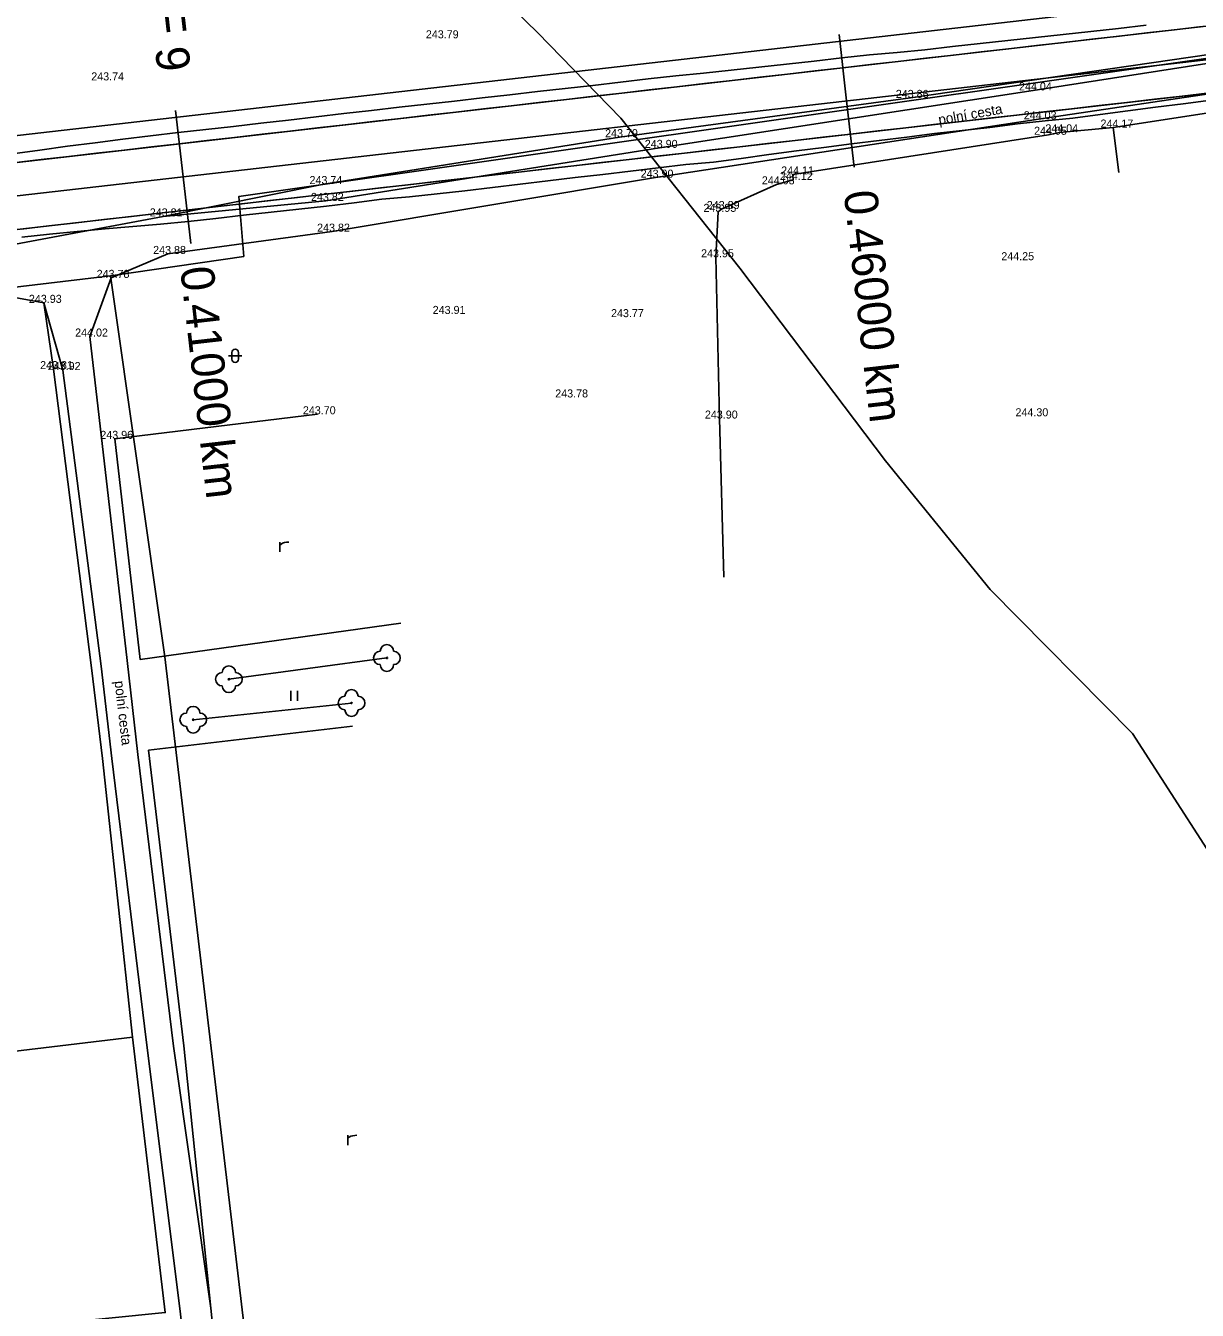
# Model space of a CAD drawing. Extents: x -555887 to -552101, y -1100251 to -1096546.
# Drawn here: x -554377.8 to -554290.1, y -1097745.7 to -1097649.6 of the extents above; entities that cross this region are included whole.
import ezdxf

# ---------------------------------------------------------------- set-up
doc = ezdxf.new("R2010")
doc.units = 0
for name, color, linetype in [('PARCELY_cesty', 7, 'Continuous'), ('POLYGONY_SITUACE_PF', 7, 'Continuous'), ('POLYGONY_SITUACE_PF_POPISY', 7, 'Continuous'), ('POLYGONY_SITUACE_PO', 7, 'Continuous'), ('vrstevnice', 7, 'Continuous'), ('Výškopis', 7, 'Continuous'), ('ZSST', 7, 'Continuous'), ('zájem', 7, 'Continuous')]:
    doc.layers.add(name, color=color, linetype=linetype)

msp = doc.modelspace()

# ---------------------------------------------------------------- linework, layer by layer
at = {"layer": 'PARCELY_cesty'}
msp.add_lwpolyline([(-554491.8, -1097670.76), (-554258.37, -1097644.02)], dxfattribs=at)
at = {"layer": 'POLYGONY_SITUACE_PF'}
for p, q in [((-554316.95, -1097650.231), (-554316.381, -1097655.199)), ((-554316.381, -1097655.199), (-554315.812, -1097660.166)), ((-554366.625, -1097655.921), (-554366.056, -1097660.888)), ((-554366.056, -1097660.888), (-554365.487, -1097665.856))]:
    msp.add_line(p, q, dxfattribs=at)
at = {"layer": 'POLYGONY_SITUACE_PO'}
for p, q in [((-554247.533, -1097644.797), (-554424.295, -1097665.042)), ((-554490.653, -1097675.159), (-554241.626, -1097646.637)), ((-554298.103, -1097650.012), (-554300.174, -1097650.233)), ((-554296.032, -1097649.785), (-554298.103, -1097650.012)), ((-554293.963, -1097649.536), (-554296.032, -1097649.785)), ((-554293.898, -1097650.108), (-554291.828, -1097649.87)), ((-554291.828, -1097649.87), (-554289.758, -1097649.633)), ((-554444.424, -1097672.38), (-554255.551, -1097650.748)), ((-554306.388, -1097650.905), (-554308.459, -1097651.133)), ((-554304.317, -1097650.68), (-554306.388, -1097650.905)), ((-554302.246, -1097650.455), (-554304.317, -1097650.68)), ((-554300.174, -1097650.233), (-554302.246, -1097650.455)), ((-554302.177, -1097651.056), (-554300.107, -1097650.819)), ((-554300.107, -1097650.819), (-554298.037, -1097650.582)), ((-554298.037, -1097650.582), (-554295.968, -1097650.345)), ((-554295.968, -1097650.345), (-554293.898, -1097650.108)), ((-554314.679, -1097651.755), (-554316.75, -1097651.981)), ((-554312.604, -1097651.561), (-554314.679, -1097651.755)), ((-554310.53, -1097651.361), (-554312.604, -1097651.561)), ((-554308.459, -1097651.133), (-554310.53, -1097651.361)), ((-554310.456, -1097652.004), (-554308.386, -1097651.767)), ((-554308.386, -1097651.767), (-554306.317, -1097651.53)), ((-554306.317, -1097651.53), (-554304.247, -1097651.293)), ((-554304.247, -1097651.293), (-554302.177, -1097651.056)), ((-554325.032, -1097652.904), (-554327.104, -1097653.115)), ((-554322.961, -1097652.674), (-554325.032, -1097652.904)), ((-554320.891, -1097652.443), (-554322.961, -1097652.674)), ((-554318.82, -1097652.212), (-554320.891, -1097652.443)), ((-554316.75, -1097651.981), (-554318.82, -1097652.212)), ((-554318.735, -1097652.952), (-554316.666, -1097652.715)), ((-554316.666, -1097652.715), (-554314.596, -1097652.478)), ((-554314.596, -1097652.478), (-554312.526, -1097652.241)), ((-554312.526, -1097652.241), (-554310.456, -1097652.004)), ((-554333.317, -1097653.803), (-554335.385, -1097654.049)), ((-554331.25, -1097653.535), (-554333.317, -1097653.803)), ((-554329.179, -1097653.313), (-554331.25, -1097653.535)), ((-554327.104, -1097653.115), (-554329.179, -1097653.313)), ((-554329.084, -1097654.138), (-554327.015, -1097653.9)), ((-554327.015, -1097653.9), (-554324.945, -1097653.663)), ((-554324.945, -1097653.663), (-554322.875, -1097653.426)), ((-554322.875, -1097653.426), (-554320.805, -1097653.189)), ((-554320.805, -1097653.189), (-554318.735, -1097652.952)), ((-554341.598, -1097654.733), (-554343.667, -1097654.974)), ((-554339.528, -1097654.495), (-554341.598, -1097654.733)), ((-554337.457, -1097654.273), (-554339.528, -1097654.495)), ((-554335.385, -1097654.049), (-554337.457, -1097654.273)), ((-554337.364, -1097655.086), (-554335.294, -1097654.849)), ((-554335.294, -1097654.849), (-554333.224, -1097654.612)), ((-554333.224, -1097654.612), (-554331.154, -1097654.375)), ((-554331.154, -1097654.375), (-554329.084, -1097654.138)), ((-554293.329, -1097655.075), (-554291.259, -1097654.838)), ((-554291.259, -1097654.838), (-554289.189, -1097654.601)), ((-554349.879, -1097655.669), (-554351.948, -1097655.906)), ((-554347.807, -1097655.451), (-554349.879, -1097655.669)), ((-554345.736, -1097655.217), (-554347.807, -1097655.451)), ((-554343.667, -1097654.974), (-554345.736, -1097655.217)), ((-554345.643, -1097656.034), (-554343.573, -1097655.797)), ((-554343.573, -1097655.797), (-554341.503, -1097655.56)), ((-554341.503, -1097655.56), (-554339.433, -1097655.323)), ((-554339.433, -1097655.323), (-554337.364, -1097655.086)), ((-554301.608, -1097656.023), (-554299.538, -1097655.786)), ((-554299.538, -1097655.786), (-554297.468, -1097655.549)), ((-554297.468, -1097655.549), (-554295.399, -1097655.312)), ((-554295.399, -1097655.312), (-554293.329, -1097655.075)), ((-554295.327, -1097655.935), (-554293.261, -1097655.67)), ((-554293.261, -1097655.67), (-554291.194, -1097655.402)), ((-554291.194, -1097655.402), (-554289.128, -1097655.135)), ((-554358.157, -1097656.627), (-554360.226, -1097656.869)), ((-554356.087, -1097656.384), (-554358.157, -1097656.627)), ((-554354.018, -1097656.143), (-554356.087, -1097656.384)), ((-554351.948, -1097655.906), (-554354.018, -1097656.143)), ((-554353.922, -1097656.982), (-554351.852, -1097656.745)), ((-554351.852, -1097656.745), (-554349.782, -1097656.508)), ((-554349.782, -1097656.508), (-554347.713, -1097656.271)), ((-554347.713, -1097656.271), (-554345.643, -1097656.034)), ((-554309.887, -1097656.972), (-554307.817, -1097656.734)), ((-554307.817, -1097656.734), (-554305.748, -1097656.497)), ((-554305.748, -1097656.497), (-554303.678, -1097656.26)), ((-554303.678, -1097656.26), (-554301.608, -1097656.023)), ((-554303.604, -1097656.908), (-554301.531, -1097656.697)), ((-554301.531, -1097656.697), (-554299.458, -1097656.485)), ((-554299.458, -1097656.485), (-554297.392, -1097656.212)), ((-554297.392, -1097656.212), (-554295.327, -1097655.935)), ((-554366.437, -1097657.563), (-554368.507, -1097657.804)), ((-554364.367, -1097657.334), (-554366.437, -1097657.563)), ((-554362.296, -1097657.104), (-554364.367, -1097657.334)), ((-554360.226, -1097656.869), (-554362.296, -1097657.104)), ((-554362.201, -1097657.93), (-554360.131, -1097657.693)), ((-554360.131, -1097657.693), (-554358.062, -1097657.456)), ((-554358.062, -1097657.456), (-554355.992, -1097657.219)), ((-554355.992, -1097657.219), (-554353.922, -1097656.982)), ((-554318.166, -1097657.92), (-554316.097, -1097657.683)), ((-554316.097, -1097657.683), (-554314.027, -1097657.446)), ((-554314.027, -1097657.446), (-554311.957, -1097657.209)), ((-554311.957, -1097657.209), (-554309.887, -1097656.972)), ((-554311.877, -1097657.905), (-554309.81, -1097657.643)), ((-554309.81, -1097657.643), (-554307.739, -1097657.419)), ((-554307.739, -1097657.419), (-554305.669, -1097657.185)), ((-554305.669, -1097657.185), (-554303.604, -1097656.908)), ((-554374.707, -1097658.591), (-554376.772, -1097658.87)), ((-554372.641, -1097658.324), (-554374.707, -1097658.591)), ((-554370.574, -1097658.062), (-554372.641, -1097658.324)), ((-554368.507, -1097657.804), (-554370.574, -1097658.062)), ((-554370.48, -1097658.879), (-554368.411, -1097658.642)), ((-554368.411, -1097658.642), (-554366.341, -1097658.405)), ((-554366.341, -1097658.405), (-554364.271, -1097658.167)), ((-554364.271, -1097658.167), (-554362.201, -1097657.93)), ((-554326.446, -1097658.868), (-554324.376, -1097658.631)), ((-554324.376, -1097658.631), (-554322.306, -1097658.394)), ((-554322.306, -1097658.394), (-554320.236, -1097658.157)), ((-554320.236, -1097658.157), (-554318.166, -1097657.92)), ((-554320.147, -1097658.936), (-554318.08, -1097658.674)), ((-554318.08, -1097658.674), (-554316.013, -1097658.413)), ((-554316.013, -1097658.413), (-554313.946, -1097658.151)), ((-554313.946, -1097658.151), (-554311.877, -1097657.905)), ((-554376.772, -1097658.87), (-554378.837, -1097659.153)), ((-554378.76, -1097659.827), (-554376.69, -1097659.59)), ((-554376.69, -1097659.59), (-554374.62, -1097659.353)), ((-554374.62, -1097659.353), (-554372.55, -1097659.116)), ((-554372.55, -1097659.116), (-554370.48, -1097658.879)), ((-554334.725, -1097659.816), (-554332.655, -1097659.579)), ((-554332.655, -1097659.579), (-554330.585, -1097659.342)), ((-554330.585, -1097659.342), (-554328.515, -1097659.105)), ((-554328.515, -1097659.105), (-554326.446, -1097658.868)), ((-554326.342, -1097659.771), (-554324.277, -1097659.495)), ((-554324.277, -1097659.495), (-554322.213, -1097659.209)), ((-554322.213, -1097659.209), (-554320.147, -1097658.936)), ((-554343.004, -1097660.764), (-554340.934, -1097660.527)), ((-554340.934, -1097660.527), (-554338.864, -1097660.29)), ((-554338.864, -1097660.29), (-554336.795, -1097660.053)), ((-554336.795, -1097660.053), (-554334.725, -1097659.816)), ((-554334.624, -1097660.699), (-554332.553, -1097660.466)), ((-554332.553, -1097660.466), (-554330.485, -1097660.216)), ((-554330.485, -1097660.216), (-554328.418, -1097659.953)), ((-554328.418, -1097659.953), (-554326.342, -1097659.771)), ((-554351.283, -1097661.713), (-554349.213, -1097661.476)), ((-554349.213, -1097661.476), (-554347.144, -1097661.239)), ((-554347.144, -1097661.239), (-554345.074, -1097661.001)), ((-554345.074, -1097661.001), (-554343.004, -1097660.764)), ((-554342.9, -1097661.677), (-554340.831, -1097661.431)), ((-554340.831, -1097661.431), (-554338.764, -1097661.168)), ((-554338.764, -1097661.168), (-554336.694, -1097660.932)), ((-554336.694, -1097660.932), (-554334.624, -1097660.699)), ((-554359.562, -1097662.661), (-554357.493, -1097662.424)), ((-554357.493, -1097662.424), (-554355.423, -1097662.187)), ((-554355.423, -1097662.187), (-554353.353, -1097661.95)), ((-554353.353, -1097661.95), (-554351.283, -1097661.713)), ((-554353.253, -1097662.82), (-554351.187, -1097662.549)), ((-554351.187, -1097662.549), (-554349.11, -1097662.377)), ((-554349.11, -1097662.377), (-554347.04, -1097662.146)), ((-554347.04, -1097662.146), (-554344.969, -1097661.915)), ((-554344.969, -1097661.915), (-554342.9, -1097661.677)), ((-554367.842, -1097663.609), (-554365.772, -1097663.372)), ((-554365.772, -1097663.372), (-554363.702, -1097663.135)), ((-554363.702, -1097663.135), (-554361.632, -1097662.898)), ((-554361.632, -1097662.898), (-554359.562, -1097662.661)), ((-554359.463, -1097663.528), (-554357.392, -1097663.303)), ((-554357.392, -1097663.303), (-554355.321, -1097663.079)), ((-554355.321, -1097663.079), (-554353.253, -1097662.82)), ((-554376.121, -1097664.557), (-554374.051, -1097664.32)), ((-554374.051, -1097664.32), (-554371.981, -1097664.083)), ((-554371.981, -1097664.083), (-554369.911, -1097663.846)), ((-554369.911, -1097663.846), (-554367.842, -1097663.609)), ((-554369.824, -1097664.606), (-554367.749, -1097664.417)), ((-554367.749, -1097664.417), (-554365.675, -1097664.22)), ((-554365.675, -1097664.22), (-554363.603, -1097664.003)), ((-554363.603, -1097664.003), (-554361.534, -1097663.755)), ((-554361.534, -1097663.755), (-554359.463, -1097663.528)), ((-554378.191, -1097664.794), (-554376.121, -1097664.557)), ((-554378.123, -1097665.382), (-554376.05, -1097665.174)), ((-554376.05, -1097665.174), (-554373.977, -1097664.971)), ((-554373.977, -1097664.971), (-554371.903, -1097664.766)), ((-554371.903, -1097664.766), (-554369.824, -1097664.606))]:
    msp.add_line(p, q, dxfattribs=at)
at = {"layer": 'vrstevnice'}
msp.add_lwpolyline([(-554347.025, -1097642.766), (-554339.532, -1097650.07), (-554333.287, -1097656.484), (-554324.367, -1097667.707), (-554313.484, -1097682.137), (-554305.633, -1097691.757), (-554294.981, -1097702.544), (-554286.519, -1097715.669), (-554277.696, -1097733.469), (-554269.053, -1097748.571), (-554262.931, -1097761.696), (-554258.429, -1097773.562), (-554253.928, -1097784.53), (-554249.066, -1097795.138), (-554243.124, -1097805.925), (-554239.79, -1097811.633), (-554234.452, -1097818.091), (-554228.293, -1097825.881), (-554221.415, -1097824.856), (-554212.484, -1097831.621)], dxfattribs=at)
at = {"layer": 'ZSST'}
for p, q in [((-554296.42, -1097657.19), (-554296.016, -1097660.556)), ((-554325.75, -1097663.29), (-554321.63, -1097661.44)), ((-554362.406, -1097674.523), (-554362.406, -1097674.023)), ((-554361.906, -1097674.523), (-554361.906, -1097674.023)), ((-554361.656, -1097674.273), (-554362.656, -1097674.273)), ((-554362.63, -1097698.48), (-554350.8, -1097696.89)), ((-554357.982, -1097700.105), (-554357.982, -1097699.355)), ((-554357.482, -1097700.105), (-554357.482, -1097699.355)), ((-554365.3, -1097701.51), (-554353.45, -1097700.26))]:
    msp.add_line(p, q, dxfattribs=at)
for points in [[(-554367.55, -1097663.84), (-554355.51, -1097661.42), (-554333.39, -1097657.91), (-554311.6, -1097654.97), (-554277.06, -1097649.95), (-554267.08, -1097648.22), (-554259.77, -1097645.47), (-554254.71, -1097640.31), (-554251.15, -1097635.05)], [(-554256.64, -1097648.34), (-554263.67, -1097648.69), (-554270.36, -1097649.56), (-554286.06, -1097651.86), (-554302.41, -1097654.41), (-554330.39, -1097658.71), (-554355.36, -1097662.68), (-554367.55, -1097663.84)], [(-554367.19, -1097666.65), (-554354.9, -1097664.98), (-554330.7, -1097660.94), (-554302.03, -1097656.57), (-554286.07, -1097654.18), (-554270.52, -1097651.57), (-554263.57, -1097650.92), (-554256.9, -1097650.3)], [(-554300.44, -1097657.55), (-554296.42, -1097657.19), (-554286.21, -1097655.61), (-554270.39, -1097653.56), (-554254.78, -1097651.65)], [(-554321.63, -1097661.44), (-554320.39, -1097661.11), (-554320.42, -1097660.7), (-554301.26, -1097657.73), (-554300.44, -1097657.55)], [(-554326.17, -1097666.9), (-554325.99, -1097663.5), (-554325.75, -1097663.29)], [(-554454.89, -1097678.09), (-554427.97, -1097673.93), (-554391.64, -1097668.01), (-554379.83, -1097666.15), (-554367.55, -1097663.84)], [(-554367.19, -1097666.65), (-554371.44, -1097668.44), (-554373.04, -1097672.83), (-554370.25, -1097697.08), (-554369.44, -1097704.12), (-554366.77, -1097725.95), (-554363.98, -1097745.55), (-554362.21, -1097763.14), (-554359.85, -1097780.61), (-554353.51, -1097814.44), (-554351.69, -1097818.85), (-554348.87, -1097819.47), (-554340.38, -1097818.88)], [(-554325.57, -1097690.83), (-554325.89, -1097678.97), (-554326.17, -1097666.9)], [(-554375.07, -1097675.34), (-554376.48, -1097670.31), (-554380.31, -1097669.62), (-554391.09, -1097670.89), (-554427.26, -1097676.93), (-554454.67, -1097680.77), (-554487.61, -1097685.6), (-554502.67, -1097687.9), (-554507.97, -1097691.12), (-554509.75, -1097693.98), (-554508.52, -1097711.87), (-554506.18, -1097742.54), (-554505.38, -1097760.57), (-554505.26, -1097765.99), (-554503.94, -1097783.38), (-554503.38, -1097798.36), (-554502.89, -1097806.7), (-554501.1, -1097825.65), (-554499.52, -1097860.36), (-554498.38, -1097882.55), (-554497.18, -1097896.97), (-554493.27, -1097934.67), (-554492.2, -1097940.22), (-554491.25, -1097941.81)], [(-554376.48, -1097670.31), (-554375.76, -1097675.27), (-554372.91, -1097697.64), (-554372.08, -1097704.42), (-554369.85, -1097725.28), (-554422.57, -1097731.58), (-554455.2, -1097735.79), (-554506.18, -1097742.54)], [(-554340.06, -1097820.97), (-554346.72, -1097821.89), (-554350.25, -1097823.77), (-554351.16, -1097827.36), (-554349.96, -1097836.43), (-554351.78, -1097836.52), (-554353.39, -1097827.68), (-554355.71, -1097814.51), (-554362.18, -1097781.05), (-554364.28, -1097763.5), (-554366.28, -1097745.77), (-554368.82, -1097725.46), (-554371.39, -1097704.41), (-554372.2, -1097697.51), (-554375.07, -1097675.34)], [(-554356, -1097678.65), (-554371.16, -1097680.49), (-554369.28, -1097697), (-554349.76, -1097694.29)], [(-554358.823, -1097688.955), (-554358.823, -1097688.223)], [(-554358.823, -1097688.459), (-554358.721, -1097688.364), (-554358.618, -1097688.301), (-554358.461, -1097688.254), (-554358.311, -1097688.231), (-554358.154, -1097688.223)], [(-554353.38, -1097701.99), (-554368.64, -1097703.8), (-554366, -1097725.91), (-554363.98, -1097745.55)], [(-554505.38, -1097760.57), (-554420.27, -1097751.2), (-554367.39, -1097745.88), (-554369.85, -1097725.28)], [(-554353.717, -1097733.347), (-554353.717, -1097732.615)], [(-554353.717, -1097732.851), (-554353.615, -1097732.756), (-554353.512, -1097732.693), (-554353.355, -1097732.646), (-554353.205, -1097732.623), (-554353.048, -1097732.615)]]:
    msp.add_lwpolyline(points, dxfattribs=at)
for centre in [(-554350.8, -1097696.89), (-554362.63, -1097698.48), (-554353.45, -1097700.26), (-554365.3, -1097701.51)]:
    msp.add_circle(centre, 0.05, dxfattribs=at)
for centre, radius, start, end in [((-554362.156, -1097674.023), 0.25, 0, 180), ((-554362.156, -1097674.523), 0.25, 180, 0), ((-554350.8, -1097696.39), 0.5, 0, 180), ((-554351.3, -1097696.89), 0.5, 90, 270), ((-554350.3, -1097696.89), 0.5, 270, 90), ((-554363.13, -1097698.48), 0.5, 90, 270), ((-554362.63, -1097697.98), 0.5, 0, 180), ((-554362.13, -1097698.48), 0.5, 270, 90), ((-554350.8, -1097697.39), 0.5, 180, 0), ((-554362.63, -1097698.98), 0.5, 180, 0), ((-554353.95, -1097700.26), 0.5, 90, 270), ((-554353.45, -1097699.76), 0.5, 0, 180), ((-554352.95, -1097700.26), 0.5, 270, 90), ((-554365.8, -1097701.51), 0.5, 90, 270), ((-554365.3, -1097701.01), 0.5, 0, 180), ((-554364.8, -1097701.51), 0.5, 270, 90), ((-554353.45, -1097700.76), 0.5, 180, 0), ((-554365.3, -1097702.01), 0.5, 180, 0)]:
    msp.add_arc(centre, radius, start, end, dxfattribs=at)
at = {"layer": 'zájem'}
for points in [[(-554254.33, -1097646.97), (-554361.88, -1097662.34), (-554361.52, -1097666.83), (-554371.48, -1097668.3), (-554500.56, -1097683.64)], [(-554187.71, -1098013.33), (-554235.08, -1098020.43), (-554238.75, -1098020.74), (-554242.36, -1098021.18), (-554261.03, -1098023.47), (-554275.16, -1097920.72), (-554275.98, -1097914.73), (-554338.17, -1097921.77), (-554343.92, -1097894.3), (-554344.86, -1097865.76), (-554349.69, -1097836.21), (-554354.15, -1097808.8), (-554357.5, -1097780.42), (-554360.83, -1097752.42), (-554364.23, -1097723.78), (-554367.43, -1097696.8), (-554371.48, -1097668.3), (-554361.52, -1097666.83), (-554361.88, -1097662.34), (-554254.33, -1097646.97)]]:
    msp.add_lwpolyline(points, dxfattribs=at)

# ---------------------------------------------------------------- texts
at = {"layer": 'POLYGONY_SITUACE_PF_POPISY'}
for s, p in [('PF 9', (-554368.757, -1097646.1)), ('0.46000 km', (-554316.606, -1097662.022)), ('0.41000 km', (-554366.281, -1097667.711))]:
    msp.add_text(s, height=2.5, rotation=276.5337, dxfattribs=at).set_placement(p)
at = {"layer": 'Výškopis'}
for s, p in [('243.79', (-554347.883, -1097650.51)), ('243.74', (-554372.933, -1097653.66)), ('244.04', (-554303.477, -1097654.41)), ('243.86', (-554312.702, -1097654.97)), ('244.03', (-554303.122, -1097656.57)), ('244.17', (-554297.375, -1097657.19)), ('243.79', (-554334.463, -1097657.91)), ('244.05', (-554302.35, -1097657.73)), ('244.04', (-554301.507, -1097657.55)), ('243.90', (-554331.492, -1097658.71)), ('243.90', (-554331.802, -1097660.94)), ('244.12', (-554321.378, -1097661.11)), ('244.11', (-554321.284, -1097660.7)), ('243.74', (-554356.593, -1097661.42)), ('244.03', (-554322.732, -1097661.44)), ('243.82', (-554356.484, -1097662.68)), ('243.81', (-554368.55, -1097663.84)), ('243.95', (-554327.098, -1097663.5)), ('243.89', (-554326.852, -1097663.29)), ('243.82', (-554356.024, -1097664.98)), ('243.88', (-554368.298, -1097666.65)), ('243.95', (-554327.278, -1097666.9)), ('244.25', (-554304.804, -1097667.12)), ('243.78', (-554372.528, -1097668.44)), ('243.93', (-554377.6, -1097670.31)), ('243.91', (-554347.372, -1097671.14)), ('243.77', (-554334.021, -1097671.38)), ('244.02', (-554374.138, -1097672.83)), ('243.81', (-554376.76, -1097675.27)), ('243.92', (-554376.186, -1097675.34)), ('243.78', (-554338.198, -1097677.39)), ('243.70', (-554357.09, -1097678.65)), ('243.90', (-554326.992, -1097678.97)), ('244.30', (-554303.742, -1097678.8)), ('243.96', (-554372.254, -1097680.49))]:
    msp.add_text(s, height=0.6, dxfattribs=at).set_placement(p)
at = {"layer": 'ZSST'}
for rotation, p in [(10.08406, (-554309.446, -1097656.988)), (276.56673, (-554371.193, -1097698.638))]:
    msp.add_text('polní cesta', height=0.75, rotation=rotation, dxfattribs=at).set_placement(p)

doc.saveas('drawing.dxf')
